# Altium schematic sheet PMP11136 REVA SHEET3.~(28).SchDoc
size 431 x 279 mm; Date: Not shown in title block; ApprovedBy: Not shown in title block; CheckedBy: Not shown in title block; Author: Not shown in title block; CompanyName: Not shown in title block; Engineer: Not shown in title block; Organization: Not shown in title block; Address1: Not shown in title block; Address2: Not shown in title block; Address3: Not shown in title block; Address4: Not shown in title block; DocumentNumber: 3; Revision: Use project parameter SCH_Rev; SheetNumber: 3; SheetTotal: 3; PageSetup: Record=PageOptions¦CenterHorizontal=True¦CenterVertical=True¦PrintScale=1.00¦XCorrection=1.00¦YCorrection=1.00¦PrintKind=0¦BorderSize=5000000¦LeftOffset=0¦BottomOffset=0¦Orientation=2¦PaperLength=1000¦PaperWidth=1000¦Scale=100¦PaperSource=15¦PrintQuality=600¦MediaType=1¦DitherType=10¦PaperKind=Letter¦PrintScaleMode=1
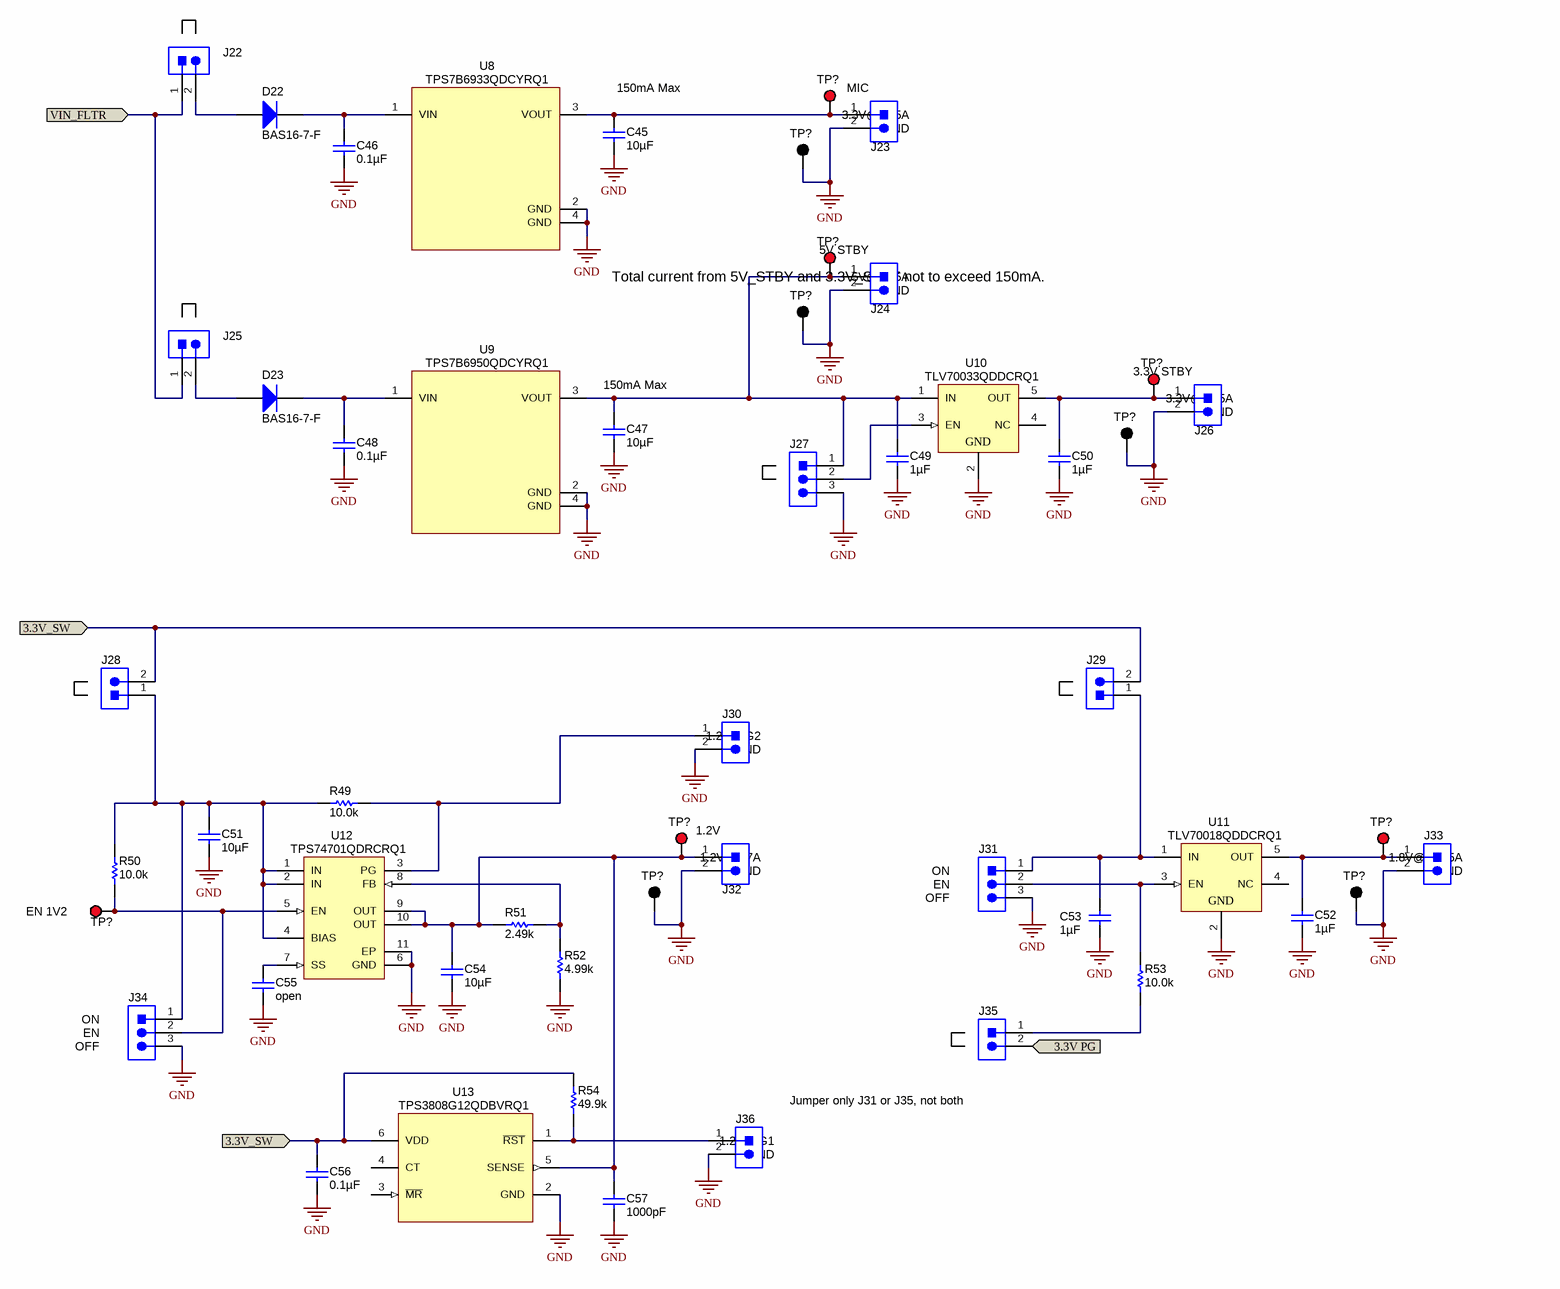
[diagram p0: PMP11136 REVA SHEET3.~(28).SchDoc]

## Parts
(Parts that share a designator on the sheet are numbered #1, #2 ... from top to bottom, then left to right.)
C45  ValueDisplayed: 10µF  [0805_HV]  (hidden comment: GRM21BR71A106KE51L)
C46  ValueDisplayed: 0.1µF  [0603]  (hidden comment: C1608X7R1H104K)
C47  ValueDisplayed: 10µF  [0805]  (hidden comment: GRM21BR71A106KE51L)
C48  ValueDisplayed: 0.1µF  [0603]  (hidden comment: C1608X7R1H104K)
C49  ValueDisplayed: 1µF  [0603]  (hidden comment: C1608X7R1E105K)
C50  ValueDisplayed: 1µF  [0603]  (hidden comment: C1608X7R1E105K)
C51  ValueDisplayed: 10µF  [0805_HV]  (hidden comment: GRM21BR71A106KE51L)
C52  ValueDisplayed: 1µF  [0603]  (hidden comment: C1608X7R1E105K)
C53  ValueDisplayed: 1µF  [0603]  (hidden comment: C1608X7R1E105K)
C54  ValueDisplayed: 10µF  [0805_HV]  (hidden comment: GRM21BR71A106KE51L)
C55  ValueDisplayed: open  [0603]
C56  ValueDisplayed: 0.1µF  [0603]  (hidden comment: C1608X7R1H104K)
C57  ValueDisplayed: 1000pF  [0603]  (hidden comment: C1608C0G2A102J)
D22  BAS16-7-F  [SOT-23]
D23  BAS16-7-F  [SOT-23]
J22  PEC02SAAN  [CONN_PEC02SAAN]  (value not drawn)
J23  ED555/2DS  [TERM_BLK_ED555-2DS]  (value not drawn)
J24  ED555/2DS  [TERM_BLK_ED555-2DS]  (value not drawn)
J25  PEC02SAAN  [CONN_PEC02SAAN]  (value not drawn)
J26  ED555/2DS  [TERM_BLK_ED555-2DS]  (value not drawn)
J27  PEC03SAAN  [CONN_PEC03SAAN]  (value not drawn)
J28  PEC02SAAN  [CONN_PEC02SAAN]  (value not drawn)
J29  PEC02SAAN  [CONN_PEC02SAAN]  (value not drawn)
J30  PEC02SAAN  [CONN_PEC02SAAN]  (value not drawn)
J31  PEC03SAAN  [CONN_PEC03SAAN]  (value not drawn)
J32  ED555/2DS  [TERM_BLK_ED555-2DS]  (value not drawn)
J33  ED555/2DS  [TERM_BLK_ED555-2DS]  (value not drawn)
J34  PEC03SAAN  [CONN_PEC03SAAN]  (value not drawn)
J35  PEC02SAAN  [CONN_PEC02SAAN]  (value not drawn)
J36  PEC02SAAN  [CONN_PEC02SAAN]  (value not drawn)
R49  ValueDisplayed: 10.0k  [0603]  (hidden comment: CRCW060310K0FKEA)
R50  ValueDisplayed: 10.0k  [0603]  (hidden comment: CRCW060310K0FKEA)
R51  ValueDisplayed: 2.49k  [0603]  (hidden comment: CRCW06032K49FKEA)
R52  ValueDisplayed: 4.99k  [0603]  (hidden comment: CRCW06034K99FKEA)
R53  ValueDisplayed: 10.0k  [0603]  (hidden comment: CRCW060310K0FKEA)
R54  ValueDisplayed: 49.9k  [0603]  (hidden comment: CRCW060349K9FKEA)
TP?#1  5000  [Keystone5000]  (value not drawn)
TP?#2  5001  [Keystone5001]  (value not drawn)
TP?#3  5000  [Keystone5000]  (value not drawn)
TP?#4  5001  [Keystone5001]  (value not drawn)
TP?#5  5000  [Keystone5000]  (value not drawn)
TP?#6  5001  [Keystone5001]  (value not drawn)
TP?#7  5000  [Keystone5000]  (value not drawn)
TP?#8  5000  [Keystone5000]  (value not drawn)
TP?#9  5001  [Keystone5001]  (value not drawn)
TP?#10  5001  [Keystone5001]  (value not drawn)
TP?#11  5000  [Keystone5000]  (value not drawn)
U8  TPS7B6933QDCYRQ1  [DCY0004A_N]
U9  TPS7B6950QDCYRQ1  [DCY0004A_N]
U10  TLV70033QDDCRQ1  [DDC0005A_N]
U11  TLV70018QDDCRQ1  [DDC0005A_N]
U12  TPS74701QDRCRQ1  [DRC0010A]
U13  TPS3808G12QDBVRQ1  [DBV0006A_N]

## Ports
3.3V PG, 3.3V_SW, VIN_FLTR

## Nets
GND: C45.2 C46.2 C47.2 C48.2 C49.2 C50.2 C51.2 C52.2 C53.2 C54.2 C55.2 C56.2 C57.2 J23.2 J24.2 J26.2 J27.3 J30.2 J31.3 J32.2 J33.2 J34.3 J36.2 R52.1 TP?#2.1 TP?#4.1 TP?#6.1 TP?#9.1 TP?#10.1 U8.2(GND) U8.4(GND) U9.2(GND) U9.4(GND) U10.2(GND) U11.2(GND) U12.6(GND) U12.11(EP) U13.2(GND)
3.3V PG: J35.2 ; port 3.3V PG
3.3V_SW: C56.1 J28.2 J29.2 R54.2 U13.6(VDD) ; port 3.3V_SW
VIN_FLTR: J22.1 J25.1 ; port VIN_FLTR
NetC45_1: C45.1 J23.1 TP?#1.1 U8.3(VOUT)
NetC46_1: C46.1 D22.3(K) U8.1(VIN)
NetC47_1: C47.1 C49.1 J24.1 J27.1 TP?#3.1 U9.3(VOUT) U10.1(IN)
NetC48_1: C48.1 D23.3(K) U9.1(VIN)
NetC50_1: C50.1 J26.1 TP?#5.1 U10.5(OUT)
NetC51_1: C51.1 J28.1 J34.1 R49.2 R50.2 U12.1(IN) U12.2(IN) U12.4(BIAS)
NetC52_1: C52.1 J33.1 TP?#8.1 U11.5(OUT)
NetC53_1: C53.1 J29.1 J31.1 U11.1(IN)
NetC54_1: C54.1 C57.1 J32.1 R51.2 TP?#7.1 U12.9(OUT) U12.10(OUT) U13.5(SENSE)
NetC55_1: C55.1 U12.7(SS)
NetD22_1: D22.1(A) J22.2
NetD23_1: D23.1(A) J25.2
NetJ27_2: J27.2 U10.3(EN)
NetJ30_1: J30.1 R49.1 U12.3(PG)
NetJ31_2: J31.2 R53.2 U11.3(EN)
NetJ34_2: J34.2 R50.1 TP?#11.1 U12.5(EN)
NetJ35_1: J35.1 R53.1
NetJ36_1: J36.1 R54.1 U13.1(~{RST})
NetR51_1: R51.1 R52.2 U12.8(FB)

Not connected (* = marked no-connect by the designer): U10 4(NC); U11 4(NC); U13 3(~{MR}) 4(CT)

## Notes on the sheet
- 150mA Max
- (near J23) MIC
- (near J23) 3.3V@0.05A
- (near J23) GND
- (near J24) 5V STBY
- (near J24) 5V@0.15A
- (near J24) GND
- Total current from 5V_STBY and 3.3V_STBY not to exceed 150mA.
- (near J26) 3.3V STBY
- (near J26) 3.3V@0.05A
- (near J26) GND
- (near J30) 1.2V_PG2
- (near J30) GND
- (near J32) 1.2V
- (near J32) 1.2V@0.7A
- (near J33) 1.8V@0.155A
- EN 1V2
- (near J32) GND
- (near J31) EN
- (near J31) ON
- (near J31) OFF
- (near J33) GND
- (near J34) EN
- (near J34) ON
- (near J34) OFF
- (near J35) Jumper only J31 or J35, not both
- (near J36) 1.2V_PG1
- (near J36) GND

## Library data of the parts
C45 C51 C54 = GRM21BR71A106KE51L: CAP, CERM, 10 µF, 10 V, +/- 10%, X7R, 0805; Manufacturer: MuRata; Polarized: N; CompType: Capacitor; Value: 10uF; U/M: EA; Cap_F: 0.00001; Tolerance_%: 10; ESR_ohm: 0.003; Value1: 0.003 ohm; Value2: 10V; TaMin_C: -55; TaMax_C: 125; Cap_Case: 0805
C46 C48 C56 = C1608X7R1H104K: CAP, CERM, 0.1uF, 50V, +/-10%, X7R, 0603; Manufacturer: TDK; Polarized: N; CompType: Capacitor; U/M: EA; Cap_F: 0.0000001; Tolerance_%: 10; ESR_Ohm: 0.017; Value1: 0.017 ohm; VDC_V: 50; TaMin_C: -55; TaMax_C: 125
C47 = GRM21BR71A106KE51L: CAP, CERM, 10uF, 10V, +/-10%, X7R, 0805; Manufacturer: MuRata; Polarized: N; CompType: Capacitor; U/M: EA; Cap_F: 0.00001; Tolerance_%: 10; ESR_Ohm: 0.003; Value1: 0.003 ohm; TaMin_C: -55; TaMax_C: 125
C49 C50 C52 C53 = C1608X7R1C105K: CAP, CERM, 1uF, 25V, +/-10%, X7R, 0603; Manufacturer: TDK; Polarized: N; CompType: Capacitor; U/M: EA; Cap_F: 0.000001; Tolerance_%: 10; ESR_Ohm: 0.0057; Value1: 0.0057 ohm; VDC_V: 25; TaMin_C: -55; TaMax_C: 125
C55 = C1608C0G1H102J: CAP, CERM, open, 0603; Polarized: N; CompType: Capacitor; U/M: EA; Cap_F: 0.000000001; Tolerance_%: 5; ESR_ohm: 0.0563; TempCo: C0G/NP0; TaMin_C: -55; TaMax_C: 125
C57 = C1608C0G2A102J: CAP, CERM, 1000 pF, 100 V, +/- 5%, C0G/NP0, 0603; Manufacturer: TDK; Polarized: N; CompType: Capacitor; Value: 1000pF; U/M: EA; Cap_F: 0.000000001; Tolerance_%: 5; ESR_ohm: 0.0589; Value1: 0.0589 ohm; VDC_V: 100; Value2: 100V; TaMin_C: -55; TaMax_C: 125
D22 D23 = BAS16-7-F: Diode, Ultrafast, 75V, 0.3A, SOT-23; Manufacturer: Diodes Inc.; U/M: EA; Vf_V: 1.125; Value2: 1.125V; Io_A: 0.3; Vr_V: 75
J22 J25 J28-J30 J35 J36 = PEC02SAAN: Header, 100mil, 2x1, Tin, TH; Manufacturer: Sullins Connector Solutions; SymbolCreator: a0412235; U/M: EA
J23 J24 J26 J32 J33 = ED555/2DS: Terminal Block, 6A, 3.5mm Pitch, 2-Pos, TH; Manufacturer: On-Shore Technology; SymbolCreator: a0412235; CompType: Connector; U/M: EA
J27 J31 J34 = PEC03SAAN: Header, 100mil, 3x1, Tin, TH; Manufacturer: Sullins Connector Solutions; SymbolCreator: a0799628; U/M: EA
R49 R50 R53 = CRCW060310K0FKEA: RES, 10.0 k, 1%, 0.1 W, 0603; Manufacturer: Vishay-Dale; CompType: Resistor; Value: 10.0k; Res_ohm: 10000; Value_Code: 10k0; Tolerance_%: 1; Power_W: 0.1; Value2: 0.1W; VDC_V: 75; TempCo: 100 ppm/C; EIA_Code: E96; U/M: EA
R51 = CRCW06032K49FKEA: RES, 2.49 k, 1%, 0.1 W, 0603; Manufacturer: Vishay-Dale; CompType: Resistor; Value: 2.49k; Res_ohm: 2490; Value_Code: 2k49; Tolerance_%: 1; Power_W: 0.1; Value2: 0.1W; VDC_V: 75; TempCo: 100 ppm/C; EIA_Code: E96; U/M: EA
R52 = CRCW06034K99FKEA: RES, 4.99 k, 1%, 0.1 W, 0603; Manufacturer: Vishay-Dale; CompType: Resistor; Value: 4.99k; Res_ohm: 4990; Value_Code: 4k99; Tolerance_%: 1; Power_W: 0.1; Value2: 0.1W; VDC_V: 75; TempCo: 100 ppm/C; EIA_Code: E96; U/M: EA
R54 = CRCW060349K9FKEA: RES, 49.9 k, 1%, 0.1 W, 0603; Manufacturer: Vishay-Dale; CompType: Resistor; Value: 49.9k; Res_ohm: 49900; Value_Code: 49k9; Tolerance_%: 1; Power_W: 0.1; Value2: 0.1W; VDC_V: 75; TempCo: 100 ppm/C; EIA_Code: E96; U/M: EA
TP?#1 TP?#3 TP?#5 TP?#7 TP?#8 TP?#11 = 5000: Test Point, Miniature, Red, TH; Manufacturer: Keystone; CompType: Test Point Loop; U/M: EA
TP?#2 TP?#4 TP?#6 TP?#9 TP?#10 = 5001: Test Point, Miniature, Black, TH; Manufacturer: Keystone; CompType: Test Point Loop; U/M: EA
U8 = TPS7B6933QDCYRQ1: High Voltage Ultra Low Iq - Low Drop Out Regulator, DCY0004A; Manufacturer: Texas Instruments; SymbolCreator: Altium; CompType: IC; U/M: EA
U9 = TPS7B6950QDCYRQ1: High Voltage Ultra Low Iq - Low Drop Out Regulator, DCY0004A; Manufacturer: Texas Instruments; SymbolCreator: Altium; CompType: IC; U/M: EA
U10 = TLV70033QDDCRQ1: Single Output Automotive LDO, 200 mA, Fixed 3.3 V Output, 2 to 5.5 V Input, with Low IQ, 5-pin SOT (DDC), -40 to 125 degC, Green (RoHS & no Sb/Br); Manufacturer: Texas Instruments; Alternate Manufacturer: None; Alternate PartNumber: Equivalent; Accuracy(%): 2; Fixed Output Options(V): 3.3; Iout(Max)(A): 0.2; Iq(Typ)(mA): 0.03; SubFamily: Single Channel LDO; Vdo(Typ)(mV): 175; Vin(Max)(V): 5.5
U11 = TLV70018QDDCRQ1: Single Output Automotive LDO, 300 mA, Fixed 1.8 V Output, 2 to 5.5 V Input, with Low IQ, 5-pin SOT (DDC), -40 to 125 degC, Green (RoHS & no Sb/Br); Manufacturer: Texas Instruments; Alternate Manufacturer: None; Alternate PartNumber: Equivalent; Accuracy(%): 2; Fixed Output Options(V): 1.8; Iout(Max)(A): 0.2; Iq(Typ)(mA): 0.03; SubFamily: Single Channel LDO; Vdo(Typ)(mV): 175; Vin(Max)(V): 5.5
U12 = TPS74701QDRCRQ1: Single Output Automotive LDO, 500 mA, Adjustable 0.8 to 3.6 V Output, 0.8 to 5.5 V Input, with Programmable Soft Start, 10-pin SON (DRC), -40 to 125 degC, Green (RoHS & no Sb/Br); Manufacturer: Texas Instruments; Alternate Manufacturer: None; Alternate PartNumber: Equivalent; Accuracy(%): 2; Iout(Max)(A): 0.5; Iq(Typ)(mA): 1; SubFamily: Single Channel LDO; Vdo(Typ)(mV): 50; Vin(Max)(V): 5.5; Vin(Min)(V): 0.8; Vout Adj(Max)(V): 3.6
U13 = TPS3808G18QDBVRQ1: LOW-QUIESCENT-CURRENT PROGRAMMABLE-DELAY SUPERVISORY CIRCUIT, DBV0006A; Manufacturer: Texas Instruments; SymbolCreator: Altium; CompType: IC; U/M: EA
